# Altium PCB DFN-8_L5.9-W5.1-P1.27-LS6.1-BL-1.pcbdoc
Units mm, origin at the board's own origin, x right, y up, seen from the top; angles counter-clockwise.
Board outline 18.12 x 19.65 mm, 2 copper layers (Top Layer, Bottom Layer), stack 0 mm thick; 1 components, 0 nets, 9 pads, 0 vias.
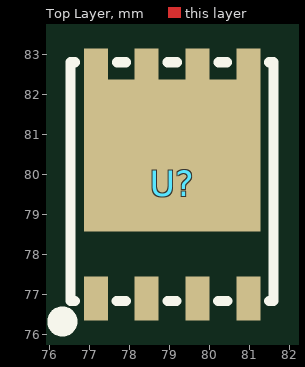
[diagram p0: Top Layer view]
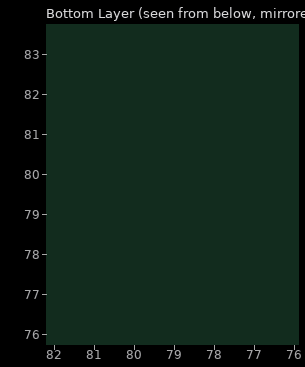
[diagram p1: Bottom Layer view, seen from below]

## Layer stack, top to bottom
Top Layer: signal copper (thickness not stored)
Bottom Layer: signal copper (thickness not stored)

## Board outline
87.967,69.85 69.85,69.85 69.85,89.502 87.967,89.502

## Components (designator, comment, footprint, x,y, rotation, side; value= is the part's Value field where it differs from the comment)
U? "" DFN-8_L5.9-W5.1-P1.27-LS6.1-BL-1 79.067,79.777 r0 top

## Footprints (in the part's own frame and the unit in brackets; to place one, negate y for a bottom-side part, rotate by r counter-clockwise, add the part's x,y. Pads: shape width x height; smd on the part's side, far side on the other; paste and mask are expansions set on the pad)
DFN-8_L5.9-W5.1-P1.27-LS6.1-BL-1 [mm]
  rect 0.6x1.1 smd paste-100 mask+0.051: 1(-1.905,-2.875) 2(-0.635,-2.875) 3(0.635,-2.875) 4(1.905,-2.875)
  rect 0.6x1 smd paste-100 mask+0.051: 5(1.905,2.875) 6(0.635,2.875) 7(-0.635,2.875) 8(-1.905,2.875)
  rect 4.41x3.8 smd paste-100 mask+0.051: 8(0,0.7)
  silkscreen extent -2.87,-3.58 2.54,3.03

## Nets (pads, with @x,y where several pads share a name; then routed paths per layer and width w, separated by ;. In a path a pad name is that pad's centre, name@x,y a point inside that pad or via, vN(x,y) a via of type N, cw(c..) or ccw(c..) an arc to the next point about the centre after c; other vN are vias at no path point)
pads on no net: U?.1 U?.2 U?.3 U?.4 U?.5 U?.6 U?.7 U?.8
